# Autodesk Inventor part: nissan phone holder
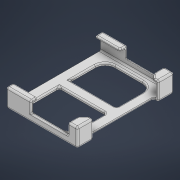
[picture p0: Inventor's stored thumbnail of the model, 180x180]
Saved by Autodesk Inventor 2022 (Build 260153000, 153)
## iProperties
Created: 2021-11
Part Number: nissan phone holder
Material: Všeobecné
Document SubType Name: Modeling
Designer: Fiji
Density: 1 g/cm^3
Appearance: Výchozí
Author: Fiji
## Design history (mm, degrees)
sketch "Náčrt1"
  geometry: L1 (0, 0)-(-22, 0); L2 (-22, 0)-(-22, -36); L3 (-22, -36)-(0, -36); L4 (0, -36)-(0, 0); L5 (-22, -11)-(-12.755, -5.4); L6 (-22, -21)-(-7.774, -14.716); C1 r 5 at (-14, -12); 2 further points
  constraints: 12 end point, 2 parallel, 2 point on line, 2 tangent, 1 centre point, 1 horizontal, 1 perpendicular
  dimensions: "d0" = 22 distance of L2.end L3.end; "d1" = 36 distance of L3.end L1.start; "d2" = 10 diameter of C1; "d3" = 12 distance from line of L1 C1.centre; "d4" = 8 distance from line of L2 C1.centre; "d5" = 11 distance from line of L1 L5.start; "d6" = 10 distance of L6.start L5.start
extrude "Vysunutí1" new body sketch "Náčrt1" distance "d7" = 0.6; taper "d8" = 0 deg
sketch "Náčrt2"
  geometry: L1 (-22, -36)-(0, -36) reference; L2 (0, -36)-(-22, -36); L3 (-22, -36)-(-22, -60); L4 (-22, -60)-(0, -60); L5 (0, -60)-(0, -36); 3 further points
  constraints: 8 end point, 2 parallel, 1 horizontal, 1 midpoint, 1 perpendicular
  dimensions: "d9" = 24 distance of L2.end L3.end
extrude "Vysunutí2" join sketch "Náčrt2" distance "d10" = 2; taper "d11" = 0 deg
node "Pracovní rovina1"
mirror "Zrcadlit1"
fillet "Zaoblení1" dims "d18" = 1, "d19" = 6, "d20" = 4
sketch "Náčrt5"
  geometry: L1 (-11.091, -2)-(35.091, -2) reference; L2 (0, 0)-(24, 0); L3 (24, 0)-(24, -2); L4 (24, -2)-(0, -2); L5 (0, -2)-(0, 0); 2 further points
  constraints: 8 end point, 2 parallel, 1 horizontal, 1 perpendicular, 1 point on line
  dimensions: "d28" = 24 distance of L3.end L4.end
extrude "Vysunutí5" join sketch "Náčrt5" distance "d29" = 58; taper "d30" = 0 deg
sketch "Náčrt6"
  geometry: L1 (0, 0)-(0, -2) reference; L2 (0, -2)-(24, -2) reference; L3 (24, -2)-(24, 0) reference; L4 (24, 0)-(0, 0) reference; L5 (-32, -2)-(56, -2) reference; L6 (12, -2)-(12, 0); L7 (-11.091, -2)-(-16.579, -2) reference; L8 (-27, -2)-(51, -2); L9 (51, -2)-(51, 13); L10 (51, 13)-(-27, 13); L11 (-27, 13)-(-27, -2); 5 further points
  constraints: 10 end point, 2 midpoint, 2 parallel, 1 horizontal, 1 perpendicular, 1 point on line, 1 other
  dimensions: "d31" = 15 distance between parallel lines of L10 L5; "d32" = 78 distance of L9.end L10.end
extrude "Vysunutí6" join sketch "Náčrt6" distance "d33" = 57.6; taper "d34" = 0 deg
sketch "Náčrt7"
  geometry: L1 (-24, 0)-(-24, -2) reference; L2 (0, 0)-(-24, 0) reference; L3 (0, -2)-(0, 0) reference; L4 (0, -2)-(27, -2) reference; L5 (27, -2)-(27, 13) reference; L6 (27, 13)-(-51, 13) reference; L7 (-51, 13)-(-51, -2) reference; L8 (-51, -2)-(-24, -2) reference; L9 (19.426, -1.4)-(29, -1.4) reference; L10 (-49.4, 11.4)-(25.4, 11.4); L11 (25.4, 11.4)-(25.4, -1.4); L12 (25.4, -1.4)-(-49.4, -1.4); L13 (-49.4, -1.4)-(-49.4, 11.4); 5 further points
  constraints: 8 end point, 2 parallel, 1 horizontal, 1 perpendicular, 1 point on line
  dimensions: "d35" = 1.6 distance between parallel lines of L5 L11; "d36" = 1.6 distance between parallel lines of L13 L7; "d37" = 1.6 distance between parallel lines of L6 L10; "d38" = 11.4 distance between parallel lines of L10 L2 (derived); "d104" = 74.8 distance between parallel lines of L11 L13 (derived)
extrude "Vysunutí7" cut sketch "Náčrt7" distance "d39" = 56; taper "d40" = 0 deg
sketch "Náčrt8"
  geometry: L1 (-57.6, 1.6)-(-57.6, 27) reference; L2 (-57.6, 1.6)-(-1.6, 1.6) reference; L3 (-1.6, 1.6)-(-1.6, 27) reference; L4 (-57.6, 27)-(-1.6, 27) reference; L5 (-57.6, 51)-(-57.6, 76.4) reference; L6 (-57.6, 51)-(-1.6, 51) reference; L7 (-1.6, 51)-(-1.6, 76.4) reference; L8 (-57.6, 76.4)-(-1.6, 76.4) reference; L9 (-57.6, 1.6)-(-1.6, 1.6) reference; L10 (-57.6, 76.4)-(-1.6, 76.4) reference; L11 (-37.6, 1.6)-(-5, 1.6); L12 (-5, 1.6)-(-5, 76.4); L13 (-5, 76.4)-(-37.6, 76.4); L14 (-37.6, 76.4)-(-37.6, 1.6); L15 (0, 78)-(0, 0) reference; L16 (-57.6, 0)-(-57.6, 78) reference; L17 (-57.6, 1.6)-(-57.6, 27) reference; L18 (-57.6, 5.6)-(-37.6, 5.6); L19 (-57.6, 78)-(-57.6, 51) reference; L20 (-57.6, 72)-(-37.6, 72); L21 (-37.6, 1.6)-(-37.6, 0); L22 (-5, 1.6)-(-5, 0); L23 (-5, 76.4)-(-5, 77); L24 (-37.6, 76.4)-(-37.6, 77); L25 (0, 78)-(0, 0) reference; L26 (0, 78)-(-57.6, 78) reference; L27 (-57.6, 0)-(-57.6, 78) reference; L28 (0, 0)-(-57.6, 0) reference; L29 (-80, 27)-(-1.6, 27) reference; L30 (-1.6, 76.4)-(-1.6, 1.6) reference; L31 (-5, 27)-(-1.6, 27); L32 (-1.6, 27)-(-1.6, 30); L33 (-1.6, 30)-(-5, 30); L34 (-5, 30)-(-5, 27); L35 (-37.6, 39)-(-80, 39); L36 (-1.6, 48)-(-5, 48); L37 (-1.6, 51)-(-1.6, 48); L38 (-5, 51)-(-1.6, 51); L39 (-5, 48)-(-5, 51); L40 (-5, 22)-(-1.6, 22); L41 (-1.6, 1.6)-(-1.6, 27) reference; L42 (-5, 56)-(-1.6, 56); L43 (-1.6, 22)-(-1.6, 56); L44 (-1.6, 51)-(-1.6, 76.4) reference; L45 (-1.6, 1.6)-(-7.6, 1.6); L46 (-7.6, 1.6)-(-7.6, 12.6); L47 (-7.6, 12.6)-(-1.6, 12.6); L48 (-1.6, 12.6)-(-1.6, 1.6); L49 (-1.6, 76.4)-(-7.6, 76.4); L50 (-7.6, 65.4)-(-1.6, 65.4); L51 (-1.6, 65.4)-(-1.6, 76.4); L52 (-7.6, 76.4)-(-7.6, 65.4); 28 further points
  constraints: 60 end point, 11 point on line, 10 symmetric about line, 6 parallel, 6 perpendicular, 4 horizontal, 4 vertical, 1 collinear, 1 midpoint
  dimensions: "d41" = 5 distance between parallel lines of L12 L15; "d42" = 20 distance between parallel lines of L14 L16; "d76" = 4.4 distance between parallel lines of L20 L10; "d77" = 4 distance between parallel lines of L2 L18; "d131" = 3 distance between parallel lines of L29 L33; "d139" = 5 distance between parallel lines of L40 L29; "d141" = 6 distance of L46.end L47.end; "d142" = 11 distance of L45.end L46.end; "d157" = 52.8 distance between parallel lines of L50 L47 (derived)
extrude "Vysunutí8" cut sketch "Náčrt8" distance "d43" = 6; taper "d44" = 0 deg
fillet "Zaoblení2" dims "d47" = 1.4, "d49" = 0.8
sketch "Náčrt10"
  geometry: L1 (-24, -1.4)-(-48.6, -1.4) reference; L2 (-24, 0)-(-24, -1.4) reference; L3 (0, 0)-(-24, 0) reference; L4 (0, -1.4)-(0, 0) reference; L5 (24.6, -1.4)-(0, -1.4) reference; L6 (24.6, 11.4)-(24.6, -1.4) reference; L7 (-24, 0)-(-24, -1.4) reference; L8 (-24, 0)-(-49.6, 0); L9 (-49.6, 11.6)-(-49.6, -2) reference; L10 (0, 0)-(-24, 0) reference; L11 (0, 0)-(28.3, 0); L12 (25.6, -2)-(25.6, 11.6) reference; L13 (24.6, -1.4)-(0, -1.4) reference; L14 (24.6, -1.4)-(25.6, -1.4); L15 (-48.6, -1.4)-(-50.036, -1.4); L16 (14.4, 11.4)-(24.6, 11.4) reference; L17 (-48.6, 11.4)-(-38.4, 11.4) reference; L18 (-38.4, 13)-(14.4, 13) reference; L19 (14.4, 13)-(14.4, 11.4) reference; L20 (-38.4, 13)-(-38.4, 11.4) reference; L21 (-48.6, -1.4)-(-48.6, 11.4) reference; L22 (-52.317, 0)-(-46.039, 0); 7 further points
  constraints: 10 end point, 3 horizontal, 3 point on line, 1 perpendicular
extrude "Vysunutí10" join sketch "Náčrt10" distance "d51" = 56; taper "d52" = 0 deg
sketch "Náčrt11"
  geometry: L1 (-32, -2)-(56, -2) reference; L2 (12, -2)-(12, 13.2); L3 (-14.4, 15)-(38.4, 15); L4 (38.4, 15)-(38.4, 0); L5 (38.4, 0)-(-14.4, 0); L6 (-14.4, 0)-(-14.4, 15); 5 further points; 1 other entity
  constraints: 10 end point, 2 parallel, 1 horizontal, 1 midpoint, 1 perpendicular, 2 other
  dimensions: "d54" = 52.8 distance of L3.start L3.end (derived); "d55" = 15 distance of L3.end L4.end; "d56" = 2 distance between parallel lines of L5 L1; "d57" = 2 dimension on L3 (derived)
extrude "Vysunutí11" cut sketch "Náčrt11" distance "d58" = 10; taper "d59" = 0 deg
sketch "Náčrt14"
  geometry: L1 (0, 48)-(90.017, 48); L2 (4, 41.6)-(30, 41.6); L3 (30, 41.6)-(30, 54.4); L4 (30, 54.4)-(4, 54.4); L5 (4, 54.4)-(4, 41.6); L6 (34, 48)-(34, 35.6); L7 (34, 35.6)-(30.4, 35.6); L8 (30.4, 35.6)-(30.4, 15); L9 (30.4, 15)-(68.6, 15); L10 (68.6, 15)-(68.6, 48); L11 (78.6, 85.6)-(78.6, 10.4) reference; L12 (30.4, 60.4)-(30.4, 81); L13 (34, 48)-(34, 60.4); L14 (30.4, 81)-(68.6, 81); L15 (68.6, 81)-(68.6, 48); L16 (34, 60.4)-(30.4, 60.4); L17 (34, 44)-(68.6, 44); L18 (34, 52)-(68.6, 52); L19 (4, 96)-(18, 96) reference; L20 (4, 0)-(18, 0) reference; L21 (80, 21.6)-(76, 21.6); L22 (76, 21.6)-(76, 74.4); L23 (76, 74.4)-(80, 74.4); L24 (80, 74.4)-(80, 21.6); L25 (22.4, 10.6)-(22.4, 36) reference; L26 (0, 60)-(0, 36) reference; L27 (78.6, 9)-(23.8, 9) reference; L28 (30.4, 35.6)-(30.4, 60.4); L29 (0, 60)-(22.4, 60) reference; L30 (22.4, 36)-(22.4, 10.4) reference; L31 (22.4, 60)-(22.4, 36); L32 (34, 44)-(18.894, 44); L33 (18.894, 44)-(18.894, 52); L34 (18.894, 52)-(34, 52); L35 (34, 52)-(34, 44); 9 further points
  constraints: 54 end point, 9 perpendicular, 6 parallel, 6 symmetric about line, 4 horizontal, 4 point on line, 1 collinear, 1 vertical, 2 other
  dimensions: "d86" = 12.8 distance of L4.end L2.start; "d87" = 26 distance between parallel lines of L3 L5; "d89" = 4 distance between parallel lines of L6 L3; "d90" = 6 distance between parallel lines of L7 L2; "d93" = 10 distance between parallel lines of L11 L10; "d100" = 4 distance between parallel lines of L17 L1; "d110" = 48 distance between parallel lines of L1 L19 (derived); "d111" = 48 distance between parallel lines of L20 L1 (derived); "d112" = 4 distance between parallel lines of L24 L22; "d113" = 8 distance between parallel lines of L8 L25; "d121" = 4 distance between parallel lines of L26 L5; "d122" = 6 distance between parallel lines of L9 L27; "d150" = 8 distance between parallel lines of L34 L32 (derived)
extrude "Vysunutí14" cut sketch "Náčrt14" extent not by distance; stored distance "d94" = 0; taper "d95" = 0 deg
fillet "Zaoblení6" dims "d96" = 4.5, "d97" = 8, "d98" = 4, "d99" = 2
fillet "Zaoblení7" dims "d105" = 1.6, "d106" = 1, "d114" = 1.6, "d115" = 1
chamfer "Zkosení1" distance "d107" = 2.4; stored, may be unused: second distance "d108" = 1.4, angle "d109" = 45 deg
fillet "Zaoblení8" dims "d119" = 1.2, "d120" = 1.6
sketch "Náčrt16"
  geometry: L1 (0, -1.4)-(54.8, -1.4) reference; L2 (8.6, 37.6)-(51.2, 37.6); L3 (14.6, 70.6)-(36.8, 70.6) reference; L4 (18.6, 2.6)-(18.6, 1.8) reference; L5 (18.6, 2.6)-(18.6, -8.366); L6 (18.6, -8.366)-(48.6, -8.366); L7 (48.6, -8.366)-(48.6, 82.125); L8 (48.6, 82.125)-(18.6, 82.125); L9 (18.6, 82.125)-(18.6, -8.366); L10 (56.2, 64)-(56.2, 75.2) reference; L11 (48.6, 75)-(48.6, 64) reference; 6 further points
  constraints: 12 end point, 3 parallel, 1 horizontal, 1 perpendicular, 1 vertical
  dimensions: "d143" = 7.6 distance between parallel lines of L10 L11 (derived); "d144" = 7.6 distance between parallel lines of L10 L7 (derived)
extrude "Vysunutí15" cut sketch "Náčrt16" distance "d127" = 9; taper "d128" = 0 deg
fillet "Zaoblení9" dims "d129" = 1, "d130" = 1.3, "d140" = 5
fillet "Zaoblení10" dims "d135" = 0.8, "d136" = 1
fillet "Zaoblení12" dims "d145" = 1
fillet "Zaoblení13" dims "d146" = 2
sketch "Náčrt17"
  geometry: L1 (-15.497, -114.541)-(22.4, -114.541); L2 (22.4, -114.541)-(22.4, 4.057); L3 (22.4, 4.057)-(-15.497, 4.057); L4 (-15.497, 4.057)-(-15.497, -114.541); L5 (22.4, -10.4)-(23.8, -10.4) reference; L6 (22.4, -10.4)-(22.4, 4.057); 1 further point
  constraints: 10 end point, 2 parallel, 1 horizontal, 1 perpendicular, 1 vertical
extrude "Vysunutí16" cut sketch "Náčrt17" stored distance "d147" = 10; taper "d148" = 0 deg
fillet "Zaoblení14" dims "d149" = 1.6
chamfer "Zkosení4" distance "d151" = 4; stored, may be unused: second distance "d152" = 2, angle "d153" = 45 deg
fillet "Zaoblení15" dims "d154" = 1, "d155" = 4
node "Těleso1"
node "Promítnutá smyčka2"
node "Promítnutá smyčka3"
node "Promítnutá smyčka4"
node "Promítnutá smyčka5"
node "Promítnutá smyčka6"
node "Promítnutá smyčka12"
